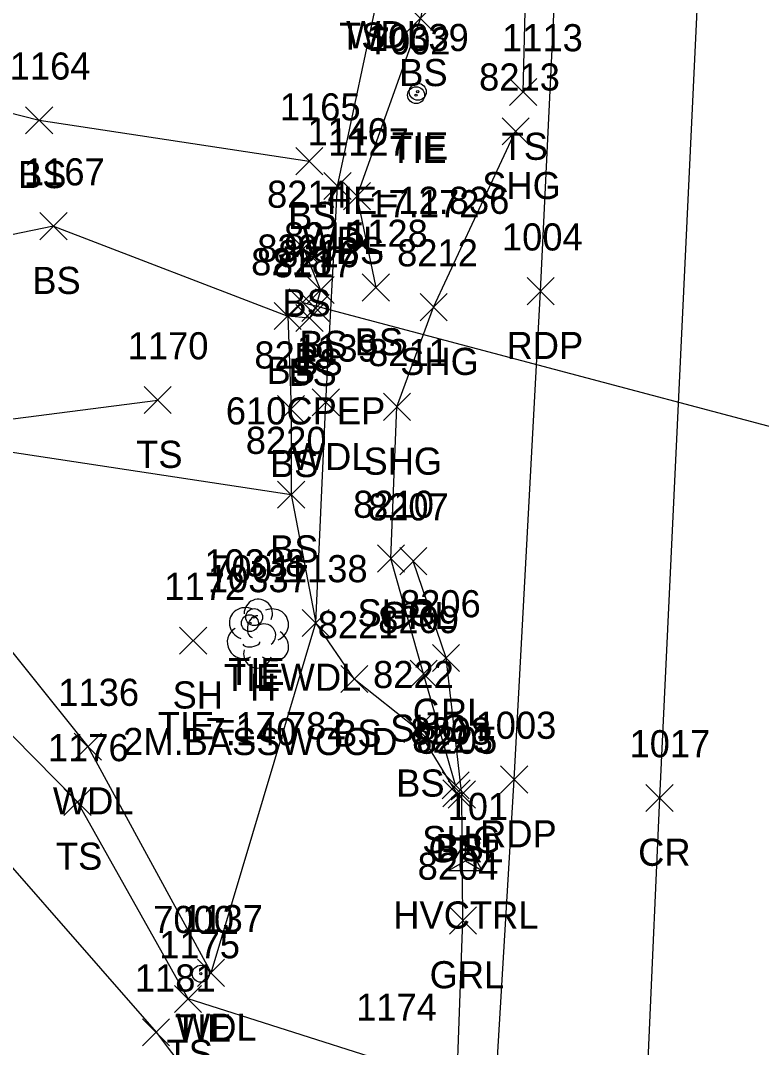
# Model space of a CAD drawing. Extents: x 1482574 to 1485769, y 580696 to 595649.
# Drawn here: x 1485120.9 to 1485175.5, y 581525.7 to 581601.3 of the extents above; entities that cross this region are included whole.
import ezdxf

# ---------------------------------------------------------------- set-up
doc = ezdxf.new("R2010")
doc.units = 0
for name, color, linetype in [('C_A', 7, 'Continuous'), ('C_C', 7, 'Continuous'), ('C_I', 7, 'Continuous'), ('CBP', 7, 'Continuous'), ('CPSM', 7, 'Continuous'), ('D_A', 7, 'Continuous'), ('D_C', 7, 'Continuous'), ('D_I', 7, 'Continuous'), ('D_TIC', 7, 'Continuous'), ('DCP', 7, 'Continuous'), ('L_A', 7, 'Continuous'), ('L_C', 7, 'Continuous'), ('L_I', 7, 'Continuous'), ('L_TIC', 7, 'Continuous'), ('LAWA', 7, 'Continuous'), ('LELB', 7, 'Continuous'), ('LTD', 7, 'Continuous'), ('P_A', 7, 'Continuous'), ('P_I', 7, 'Continuous'), ('P_TIC', 7, 'Continuous'), ('PET', 7, 'Continuous'), ('PRC', 7, 'Continuous'), ('PSU', 7, 'Continuous'), ('R_A', 7, 'Continuous'), ('R_I', 7, 'Continuous'), ('R_TIC', 7, 'Continuous'), ('RGR', 7, 'Continuous')]:
    doc.layers.add(name, color=color, linetype=linetype)

msp = doc.modelspace()

# ---------------------------------------------------------------- linework, layer by layer
at = {"layer": 'CBP'}
for centre, radius in [((1485150.166, 581596.091), 0.625), ((1485150.042, 581595.841), 0.625), ((1485150.042, 581595.841), 0.0833), ((1485150.166, 581596.091), 0.0833), ((1485138.115, 581557.372), 0.625), ((1485137.801, 581556.927), 0.625), ((1485138.115, 581557.372), 0.0833), ((1485137.801, 581556.927), 0.0833), ((1485134.185, 581531.094), 0.625), ((1485134.185, 581531.094), 0.0833)]:
    msp.add_circle(centre, radius, dxfattribs=at)
at = {"layer": 'CPSM'}
for p, q in [((1485152.42, 581538.7), (1485153.67, 581540.865)), ((1485152.42, 581538.7), (1485153.67, 581540.865)), ((1485152.42, 581538.7), (1485153.67, 581540.865)), ((1485152.42, 581538.7), (1485153.67, 581540.865)), ((1485152.42, 581538.7), (1485153.67, 581540.865)), ((1485152.42, 581538.7), (1485153.67, 581540.865)), ((1485152.42, 581538.7), (1485153.67, 581540.865)), ((1485152.42, 581538.7), (1485153.67, 581540.865)), ((1485154.92, 581538.7), (1485153.67, 581540.865)), ((1485153.67, 581539.421), (1485153.67, 581540.865)), ((1485154.92, 581538.7), (1485153.67, 581540.865)), ((1485153.67, 581539.421), (1485153.67, 581540.865)), ((1485154.92, 581538.7), (1485153.67, 581540.865)), ((1485153.67, 581539.421), (1485153.67, 581540.865)), ((1485154.92, 581538.7), (1485153.67, 581540.865)), ((1485153.67, 581539.421), (1485153.67, 581540.865)), ((1485154.92, 581538.7), (1485153.67, 581540.865)), ((1485153.67, 581539.421), (1485153.67, 581540.865)), ((1485154.92, 581538.7), (1485153.67, 581540.865)), ((1485153.67, 581539.421), (1485153.67, 581540.865)), ((1485154.92, 581538.7), (1485153.67, 581540.865)), ((1485153.67, 581539.421), (1485153.67, 581540.865)), ((1485154.92, 581538.7), (1485153.67, 581540.865)), ((1485153.67, 581539.421), (1485153.67, 581540.865)), ((1485152.42, 581538.7), (1485153.67, 581539.421)), ((1485152.42, 581538.7), (1485153.67, 581539.421)), ((1485152.42, 581538.7), (1485153.67, 581539.421)), ((1485152.42, 581538.7), (1485153.67, 581539.421)), ((1485152.42, 581538.7), (1485153.67, 581539.421)), ((1485152.42, 581538.7), (1485153.67, 581539.421)), ((1485152.42, 581538.7), (1485153.67, 581539.421)), ((1485152.42, 581538.7), (1485153.67, 581539.421)), ((1485153.67, 581539.421), (1485153.67, 581539.421)), ((1485153.67, 581539.421), (1485154.92, 581538.7)), ((1485153.67, 581539.421), (1485153.67, 581539.421)), ((1485153.67, 581539.421), (1485154.92, 581538.7)), ((1485153.67, 581539.421), (1485153.67, 581539.421)), ((1485153.67, 581539.421), (1485154.92, 581538.7)), ((1485153.67, 581539.421), (1485153.67, 581539.421)), ((1485153.67, 581539.421), (1485154.92, 581538.7)), ((1485153.67, 581539.421), (1485153.67, 581539.421)), ((1485153.67, 581539.421), (1485154.92, 581538.7)), ((1485153.67, 581539.421), (1485153.67, 581539.421)), ((1485153.67, 581539.421), (1485154.92, 581538.7)), ((1485153.67, 581539.421), (1485153.67, 581539.421)), ((1485153.67, 581539.421), (1485154.92, 581538.7)), ((1485153.67, 581539.421), (1485153.67, 581539.421)), ((1485153.67, 581539.421), (1485154.92, 581538.7)), ((1485152.42, 581538.7), (1485154.92, 581538.7)), ((1485152.42, 581538.7), (1485154.92, 581538.7)), ((1485152.42, 581538.7), (1485154.92, 581538.7)), ((1485152.42, 581538.7), (1485154.92, 581538.7)), ((1485152.42, 581538.7), (1485154.92, 581538.7)), ((1485152.42, 581538.7), (1485154.92, 581538.7)), ((1485152.42, 581538.7), (1485154.92, 581538.7)), ((1485152.42, 581538.7), (1485154.92, 581538.7))]:
    msp.add_line(p, q, dxfattribs=at)
at = {"layer": 'D_TIC'}
for points in [[(1485140.689, 581579.572), (1485142.689, 581581.572)], [(1485142.689, 581579.572), (1485140.689, 581581.572)]]:
    msp.add_lwpolyline(points, dxfattribs=at)
at = {"layer": 'DCP'}
msp.add_lwpolyline([(1485141.689, 581580.572), (1485195.215, 581566.357)], dxfattribs=at)
at = {"layer": 'L_TIC'}
for points in [[(1485149.356, 581600.507), (1485151.356, 581602.507)], [(1485151.356, 581600.507), (1485149.356, 581602.507)], [(1485156.932, 581595.074), (1485158.932, 581597.074)], [(1485158.932, 581595.074), (1485156.932, 581597.074)], [(1485121.282, 581592.988), (1485123.282, 581594.988)], [(1485123.282, 581592.988), (1485121.282, 581594.988)], [(1485141.177, 581589.979), (1485143.177, 581591.979)], [(1485143.177, 581589.979), (1485141.177, 581591.979)], [(1485143.254, 581588.145), (1485145.254, 581590.145)], [(1485145.254, 581588.145), (1485143.254, 581590.145)], [(1485144.685, 581587.394), (1485146.685, 581589.394)], [(1485146.685, 581587.394), (1485144.685, 581589.394)], [(1485122.329, 581585.189), (1485124.329, 581587.189)], [(1485124.329, 581585.189), (1485122.329, 581587.189)], [(1485140.757, 581583.542), (1485142.757, 581585.542)], [(1485142.757, 581583.542), (1485140.757, 581585.542)], [(1485142.007, 581580.475), (1485144.007, 581582.475)], [(1485144.007, 581580.475), (1485142.007, 581582.475)], [(1485146.079, 581580.665), (1485148.079, 581582.665)], [(1485148.079, 581580.665), (1485146.079, 581582.665)], [(1485141.633, 581579.162), (1485143.633, 581581.162)], [(1485143.633, 581579.162), (1485141.633, 581581.162)], [(1485139.586, 581578.562), (1485141.586, 581580.562)], [(1485141.586, 581578.562), (1485139.586, 581580.562)], [(1485141.187, 581578.418), (1485143.187, 581580.418)], [(1485143.187, 581578.418), (1485141.187, 581580.418)], [(1485130.013, 581572.371), (1485132.013, 581574.371)], [(1485132.013, 581572.371), (1485130.013, 581574.371)], [(1485142.398, 581572.204), (1485144.398, 581574.204)], [(1485144.398, 581572.204), (1485142.398, 581574.204)], [(1485139.832, 581571.695), (1485141.832, 581573.695)], [(1485141.832, 581571.695), (1485139.832, 581573.695)], [(1485139.845, 581565.402), (1485141.845, 581567.402)], [(1485141.845, 581565.402), (1485139.845, 581567.402)], [(1485141.65, 581555.944), (1485143.65, 581557.944)], [(1485143.65, 581555.944), (1485141.65, 581557.944)], [(1485132.618, 581554.638), (1485134.618, 581556.638)], [(1485134.618, 581554.638), (1485132.618, 581556.638)], [(1485144.491, 581551.817), (1485146.491, 581553.817)], [(1485146.491, 581551.817), (1485144.491, 581553.817)], [(1485149.133, 581548.145), (1485151.133, 581550.145)], [(1485151.133, 581548.145), (1485149.133, 581550.145)], [(1485124.868, 581546.833), (1485126.868, 581548.833)], [(1485126.868, 581546.833), (1485124.868, 581548.833)], [(1485152.014, 581543.388), (1485154.014, 581545.388)], [(1485154.014, 581543.388), (1485152.014, 581545.388)], [(1485124.101, 581542.755), (1485126.101, 581544.755)], [(1485126.101, 581542.755), (1485124.101, 581544.755)], [(1485133.94, 581530.156), (1485135.94, 581532.156)], [(1485135.94, 581530.156), (1485133.94, 581532.156)], [(1485132.247, 581528.231), (1485134.247, 581530.231)], [(1485134.247, 581528.231), (1485132.247, 581530.231)], [(1485129.885, 581525.78), (1485131.885, 581527.78)], [(1485131.885, 581525.78), (1485129.885, 581527.78)]]:
    msp.add_lwpolyline(points, dxfattribs=at)
at = {"layer": 'LAWA'}
msp.add_lwpolyline([(1485108.07, 581570.041), (1485125.868, 581547.833), (1485134.94, 581531.156), (1485142.65, 581556.944), (1485143.398, 581573.204), (1485144.254, 581589.145), (1485147.473, 581604.303), (1485148.503, 581640.441), (1485148.831, 581678.643), (1485151.856, 581716.96), (1485152.089, 581754.178), (1485152.053, 581788.521), (1485152.505, 581804.942)], dxfattribs=at)
at = {"layer": 'LELB'}
for points in [[(1485153.667, 581804.909), (1485158.775, 581768.551), (1485159.156, 581730.316), (1485159.015, 581691.73), (1485157.338, 581653.476), (1485153.578, 581616.232), (1485150.356, 581601.507), (1485145.685, 581588.394), (1485147.079, 581581.665)], [(1485157.932, 581596.074), (1485158.788, 581630.854), (1485160.924, 581666.583), (1485161.866, 581702.213), (1485163.299, 581738.066), (1485165.396, 581774.375), (1485166.344, 581804.716)], [(1485101.754, 581599.24), (1485122.282, 581593.988), (1485142.177, 581590.979)], [(1485123.329, 581586.189), (1485107.955, 581583.017)], [(1485123.329, 581586.189), (1485140.586, 581579.562)], [(1485141.757, 581584.542), (1485143.007, 581581.475), (1485142.633, 581580.162), (1485142.187, 581579.418), (1485140.586, 581579.562), (1485140.832, 581572.695), (1485140.845, 581566.402)], [(1485111.557, 581570.851), (1485131.013, 581573.371)], [(1485111.557, 581570.851), (1485140.845, 581566.402)], [(1485140.845, 581566.402), (1485142.65, 581556.944)], [(1485147.751, 581524.628), (1485133.247, 581529.231), (1485125.101, 581543.755), (1485117.181, 581551.783), (1485108.181, 581566.133)], [(1485145.491, 581552.817), (1485142.65, 581556.944)], [(1485145.491, 581552.817), (1485150.133, 581549.145), (1485153.014, 581544.388)], [(1485114.3, 581545.75), (1485130.885, 581526.78), (1485143.175, 581510.494)]]:
    msp.add_lwpolyline(points, dxfattribs=at)
at = {"layer": 'LTD'}
msp.add_line((1485138.373, 581556.209), (1485138.373, 581556.209), dxfattribs=at)
msp.add_line((1485138.373, 581556.209), (1485138.373, 581556.209), dxfattribs=at)
msp.add_arc((1485138.42, 581557.643), 1.047, 335.52715, 180.95627, dxfattribs=at)
for centre, major_axis, ratio, start_param, end_param in [((1485137.581, 581556.875), (1.21, -0.512), 0.895232, 1.570796, 4.712389), ((1485139.415, 581556.792), (-1.141, -0.483), 0.949671, 1.570796, 4.712389), ((1485138.165, 581556.667), (-0.208, -0.792), 0.645439, 3.141593, 6.283185), ((1485137.29, 581555.5), (0.584, -1.042), 0.959034, 3.141593, 6.283185), ((1485138.873, 581556.042), (-0.5, 0.667), 0.989748, 3.141593, 6.283185), ((1485139.373, 581555.375), (-1.09, 0.792), 0.841452, 1.570796, 4.712389), ((1485138.373, 581554.709), (0.265, 1.061), 0.942809, 1.570796, 4.712389), ((1485137.915, 581555.459), (-0.625, -0.083), 0.423636, 0, 3.141593)]:
    msp.add_ellipse(centre, major_axis=major_axis, ratio=ratio, start_param=start_param, end_param=end_param, dxfattribs=at)
at = {"layer": 'P_TIC'}
for points in [[(1485156.377, 581592.181), (1485158.377, 581594.181)], [(1485158.377, 581592.181), (1485156.377, 581594.181)], [(1485158.218, 581580.393), (1485160.218, 581582.393)], [(1485160.218, 581580.393), (1485158.218, 581582.393)], [(1485150.337, 581579.221), (1485152.337, 581581.221)], [(1485152.337, 581579.221), (1485150.337, 581581.221)], [(1485147.631, 581571.869), (1485149.631, 581573.869)], [(1485149.631, 581571.869), (1485147.631, 581573.869)], [(1485147.188, 581560.691), (1485149.188, 581562.691)], [(1485149.188, 581560.691), (1485147.188, 581562.691)], [(1485149.599, 581552.191), (1485151.599, 581554.191)], [(1485151.599, 581552.191), (1485149.599, 581554.191)], [(1485151.955, 581543.982), (1485153.955, 581545.982)], [(1485153.955, 581543.982), (1485151.955, 581545.982)], [(1485156.269, 581544.405), (1485158.269, 581546.405)], [(1485158.269, 581544.405), (1485156.269, 581546.405)], [(1485166.968, 581543.044), (1485168.968, 581545.044)], [(1485168.968, 581543.044), (1485166.968, 581545.044)]]:
    msp.add_lwpolyline(points, dxfattribs=at)
at = {"layer": 'PET'}
msp.add_lwpolyline([(1485155.097, 581509.329), (1485157.269, 581545.405), (1485159.218, 581581.393), (1485160.95, 581617.616), (1485162.548, 581653.085), (1485164.08, 581689.444), (1485165.258, 581725.402), (1485166.423, 581761.382), (1485167.62, 581795.834)], dxfattribs=at)
at = {"layer": 'PRC'}
msp.add_lwpolyline([(1485179.277, 581795.342), (1485177.791, 581760.444), (1485176.068, 581724.188), (1485174.438, 581687.505), (1485172.879, 581651.786), (1485171.291, 581614.06), (1485167.968, 581544.044), (1485166.351, 581507.59)], dxfattribs=at)
at = {"layer": 'PSU'}
msp.add_lwpolyline([(1485152.955, 581544.982), (1485150.599, 581553.191), (1485148.188, 581561.691), (1485148.631, 581572.869), (1485151.337, 581580.221), (1485157.377, 581593.181)], dxfattribs=at)
at = {"layer": 'R_TIC'}
for points in [[(1485148.835, 581560.498), (1485150.835, 581562.498)], [(1485150.835, 581560.498), (1485148.835, 581562.498)], [(1485151.25, 581553.362), (1485153.25, 581555.362)], [(1485153.25, 581553.362), (1485151.25, 581555.362)], [(1485152.411, 581543.3), (1485154.411, 581545.3)], [(1485154.411, 581543.3), (1485152.411, 581545.3)], [(1485152.496, 581534.018), (1485154.496, 581536.018)], [(1485154.496, 581534.018), (1485152.496, 581536.018)]]:
    msp.add_lwpolyline(points, dxfattribs=at)
at = {"layer": 'RGR'}
msp.add_lwpolyline([(1485152.765, 581515.402), (1485153.496, 581535.018), (1485153.411, 581544.3), (1485152.25, 581554.362), (1485149.835, 581561.498)], dxfattribs=at)

# ---------------------------------------------------------------- texts
at = {"layer": 'C_A'}
for s, p in [('TIE', (1485148.121, 581590.841)), ('TIE', (1485148.245, 581591.091)), ('TIE', (1485136.194, 581552.372)), ('TIE', (1485135.88, 581551.927)), ('HVCTRL', (1485148.363, 581534.421)), ('HVCTRL', (1485148.363, 581534.421)), ('HVCTRL', (1485148.363, 581534.421)), ('HVCTRL', (1485148.363, 581534.421)), ('HVCTRL', (1485148.363, 581534.421)), ('HVCTRL', (1485148.363, 581534.421)), ('HVCTRL', (1485148.363, 581534.421)), ('HVCTRL', (1485148.363, 581534.421)), ('TIE', (1485132.264, 581526.094))]:
    msp.add_text(s, height=2, dxfattribs=at).set_placement(p)
at = {"layer": 'C_C'}
for s, p in [('TIE=12.836', (1485143.009, 581587.091)), ('17.172', (1485146.53, 581586.841)), ('TIE=17.782', (1485131.013, 581548.372)), ('7.140', (1485134.533, 581547.927))]:
    msp.add_text(s, height=2, dxfattribs=at).set_placement(p)
at = {"layer": 'C_I'}
for s, p in [('10339', (1485146.489, 581599.091)), ('7002', (1485146.625, 581598.841)), ('10338', (1485134.446, 581560.372)), ('7001', (1485134.951, 581559.927)), ('101', (1485152.363, 581542.421)), ('101', (1485152.363, 581542.421)), ('101', (1485152.363, 581542.421)), ('101', (1485152.363, 581542.421)), ('101', (1485152.363, 581542.421)), ('101', (1485152.363, 581542.421)), ('101', (1485152.363, 581542.421)), ('101', (1485152.363, 581542.421)), ('7000', (1485130.681, 581534.094))]:
    msp.add_text(s, height=2, dxfattribs=at).set_placement(p)
at = {"layer": 'D_A'}
msp.add_text('P', height=2, dxfattribs=at).set_placement((1485141.067, 581575.572))
at = {"layer": 'D_C'}
msp.add_text('610CPEP', height=2, dxfattribs=at).set_placement((1485136.028, 581571.572))
at = {"layer": 'D_I'}
msp.add_text('8309', height=2, dxfattribs=at).set_placement((1485138.343, 581583.572))
at = {"layer": 'L_A'}
for s, p in [('TS', (1485144.372, 581599.194)), ('WDL', (1485144.89, 581599.303)), ('BS', (1485148.797, 581596.507)), ('TS', (1485156.341, 581591.074)), ('BS', (1485120.723, 581588.988)), ('BS', (1485140.618, 581585.979)), ('WDL', (1485141.671, 581584.145)), ('BS', (1485144.126, 581583.394)), ('BS', (1485121.77, 581581.189)), ('BS', (1485140.198, 581579.542)), ('BS', (1485141.448, 581576.475)), ('BS', (1485145.52, 581576.665)), ('BS', (1485141.074, 581575.162)), ('BS', (1485139.027, 581574.562)), ('BS', (1485140.628, 581574.418)), ('TS', (1485129.422, 581568.371)), ('WDL', (1485140.815, 581568.204)), ('BS', (1485139.273, 581567.695)), ('BS', (1485139.286, 581561.402)), ('WDL', (1485140.067, 581551.944)), ('H', (1485137.806, 581551.209)), ('SH', (1485132.106, 581550.638)), ('BS', (1485143.932, 581547.817)), ('BS', (1485148.574, 581544.145)), ('WDL', (1485123.285, 581542.833)), ('BS', (1485151.455, 581539.388)), ('TS', (1485123.51, 581538.755)), ('WDL', (1485132.357, 581526.156)), ('TS', (1485131.656, 581524.231))]:
    msp.add_text(s, height=2, dxfattribs=at).set_placement(p)
at = {"layer": 'L_C'}
msp.add_text('2M.BASSWOOD', height=2, dxfattribs=at).set_placement((1485128.46, 581547.209))
at = {"layer": 'L_I'}
for s, p in [('1113', (1485156.373, 581599.074)), ('1164', (1485120.109, 581596.988)), ('1165', (1485140.004, 581593.979)), ('1140', (1485142.041, 581592.145)), ('1127', (1485143.559, 581591.394)), ('1167', (1485121.156, 581589.189)), ('8214', (1485139.064, 581587.542)), ('8215', (1485140.314, 581584.475)), ('1128', (1485144.953, 581584.665)), ('8218', (1485137.893, 581582.562)), ('8216', (1485139.885, 581583.162)), ('8217', (1485139.494, 581582.418)), ('1170', (1485128.8, 581576.371)), ('8219', (1485138.131, 581575.695)), ('1139', (1485141.264, 581576.204)), ('8220', (1485137.499, 581569.402)), ('1138', (1485140.524, 581559.944)), ('10337', (1485134.704, 581559.209)), ('1172', (1485131.492, 581558.638)), ('8221', (1485142.798, 581555.817)), ('8222', (1485146.873, 581552.145)), ('1136', (1485123.687, 581550.833)), ('8223', (1485149.754, 581547.388)), ('1176', (1485122.92, 581546.755)), ('1137', (1485132.814, 581534.156)), ('1175', (1485131.121, 581532.231)), ('1181', (1485129.326, 581529.78)), ('1174', (1485145.625, 581527.628))]:
    msp.add_text(s, height=2, dxfattribs=at).set_placement(p)
at = {"layer": 'P_A'}
for s, p in [('SHG', (1485154.912, 581588.181)), ('RDP', (1485156.706, 581576.393)), ('SHG', (1485148.872, 581575.221)), ('SHG', (1485146.166, 581567.869)), ('SHG', (1485145.723, 581556.691)), ('SHG', (1485148.134, 581548.191)), ('RDP', (1485154.757, 581540.405)), ('SHG', (1485150.49, 581539.982)), ('CR', (1485166.401, 581539.044))]:
    msp.add_text(s, height=2, dxfattribs=at).set_placement(p)
at = {"layer": 'P_I'}
for s, p in [('8213', (1485154.684, 581596.181)), ('1004', (1485156.368, 581584.393)), ('8212', (1485148.644, 581583.221)), ('8211', (1485146.505, 581575.869)), ('8210', (1485145.408, 581564.691)), ('8209', (1485147.253, 581556.191)), ('1003', (1485154.419, 581548.405)), ('8208', (1485149.616, 581547.982)), ('1017', (1485165.763, 581547.044))]:
    msp.add_text(s, height=2, dxfattribs=at).set_placement(p)
at = {"layer": 'R_A'}
for p in [(1485147.378, 581556.498), (1485149.793, 581549.362), (1485150.954, 581539.3), (1485151.039, 581530.018)]:
    msp.add_text('GRL', height=2, dxfattribs=at).set_placement(p)
at = {"layer": 'R_I'}
for s, p in [('8207', (1485146.496, 581564.498)), ('8206', (1485148.856, 581557.362)), ('8205', (1485150.072, 581547.3)), ('8204', (1485150.157, 581538.018))]:
    msp.add_text(s, height=2, dxfattribs=at).set_placement(p)

doc.saveas('drawing.dxf')
